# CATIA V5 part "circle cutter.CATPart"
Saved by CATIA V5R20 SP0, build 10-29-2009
Part number: cc
Bounding box of the stored display mesh (mm): x 0 to 5, y -130 to 130, z -129.809 to 129.809
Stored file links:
  C:\Users\khanm\Downloads\Catia Project\Catia Project\circle cutter.CATPart
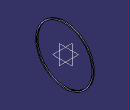
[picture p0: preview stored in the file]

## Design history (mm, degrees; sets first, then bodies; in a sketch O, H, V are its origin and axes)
Body1 (main body)
  Sketch1 on yz-plane, origin (0, 0, 0), H (0, 1, 0), V (0, 0, 1)
    circle A1 centre (0, 0) radius 130
    radius A1 = 130
  Pad1: profile Sketch1, direction (1, 0, 0), length 5
  Sketch2 on end face of Pad1, origin (5, 0, 0), H (0, 1, 0), V (0, 0, 1)
    circle A1 centre (0, 0) radius 125
    radius A1 = 125
  Pocket1: profile Sketch2, direction (-1, 0, 0), through (limit type 3)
